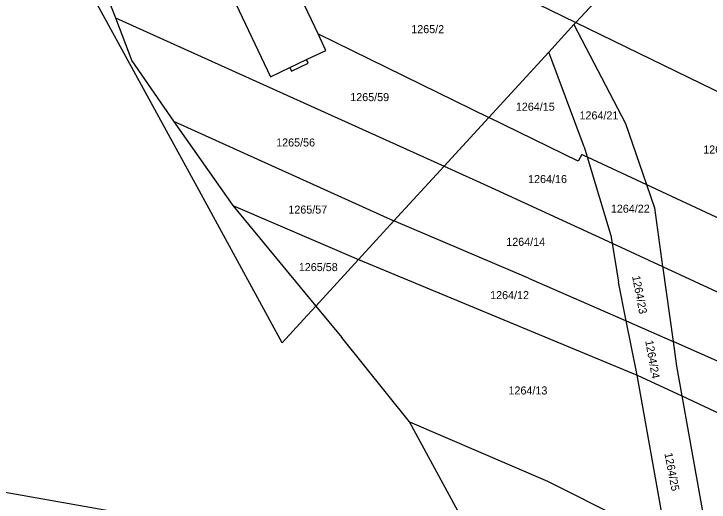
# Model space of a CAD drawing. Extents: x -779618 to -776429, y -1144546 to -1143350.
# Drawn here: x -777222.5 to -777075.6, y -1144217.4 to -1144114.1 of the extents above; entities that cross this region are included whole.
import ezdxf

# ---------------------------------------------------------------- set-up
doc = ezdxf.new("R2010")
doc.units = 0
for name, color, linetype in [('1', 7, 'Continuous'), ('11', 7, 'Continuous'), ('12', 7, 'Continuous'), ('2', 7, 'Continuous'), ('4', 7, 'Continuous')]:
    doc.layers.add(name, color=color, linetype=linetype)

msp = doc.modelspace()

# ---------------------------------------------------------------- linework, layer by layer
at = {"layer": '1'}
for p, q in [((-777158.22, -1144118.36), (-777176.03, -1144080.61)), ((-777209.36, -1144093.35), (-777201.02, -1144114.97)), ((-777103.71, -1144115.92), (-777089.82, -1144101.04)), ((-777130.33, -1144102.93), (-777103.71, -1144115.92)), ((-777183.36, -1144151.49), (-777207.58, -1144107.1)), ((-777176.85, -1144109.25), (-777168.29, -1144127.4)), ((-777201.02, -1144114.97), (-777131.57, -1144146.34)), ((-777201.02, -1144114.97), (-777197.6, -1144124.07)), ((-777109.45, -1144122.24), (-777104.14, -1144116.38)), ((-777104.14, -1144116.38), (-777103.71, -1144115.92)), ((-777104.14, -1144116.38), (-777093.24, -1144137.31)), ((-777103.71, -1144115.92), (-777052.04, -1144141.15)), ((-777158.22, -1144118.36), (-777122.09, -1144136.02)), ((-777156.57, -1144121.86), (-777158.22, -1144118.36)), ((-777160.64, -1144123.78), (-777156.57, -1144121.86)), ((-777122.09, -1144136.02), (-777109.45, -1144122.24)), ((-777101.97, -1144142.24), (-777109.45, -1144122.24)), ((-777197.6, -1144124.07), (-777188.78, -1144136.82)), ((-777160.28, -1144124.54), (-777160.64, -1144123.78)), ((-777168.29, -1144127.4), (-777164.2, -1144125.47)), ((-777164.2, -1144125.47), (-777163.84, -1144126.23)), ((-777163.84, -1144126.23), (-777160.28, -1144124.54)), ((-777188.78, -1144136.82), (-777176.23, -1144154.67)), ((-777188.78, -1144136.82), (-777142.17, -1144157.9)), ((-777131.57, -1144146.34), (-777122.09, -1144136.02)), ((-777103.26, -1144145.23), (-777122.09, -1144136.02)), ((-777093.24, -1144137.31), (-777088.81, -1144150.2)), ((-777101.97, -1144142.24), (-777101.34, -1144144.35)), ((-777102.45, -1144143.83), (-777103.26, -1144145.23)), ((-777102.45, -1144143.83), (-777101.34, -1144144.35)), ((-777101.34, -1144144.35), (-777088.81, -1144150.2)), ((-777101.34, -1144144.35), (-777096.34, -1144160.95)), ((-777142.17, -1144157.9), (-777131.57, -1144146.34)), ((-777131.57, -1144146.34), (-777121.63, -1144150.83)), ((-777088.81, -1144150.2), (-777061.29, -1144163.05)), ((-777088.81, -1144150.2), (-777087.12, -1144155.11)), ((-777165.81, -1144183.66), (-777183.36, -1144151.49)), ((-777121.63, -1144150.83), (-777096.06, -1144162.63)), ((-777176.23, -1144154.67), (-777158.69, -1144175.9)), ((-777176.23, -1144154.67), (-777149.69, -1144166.09)), ((-777087.12, -1144155.11), (-777085.38, -1144167.56)), ((-777149.69, -1144166.09), (-777142.17, -1144157.9)), ((-777113.7, -1144169.98), (-777142.17, -1144157.9)), ((-777096.34, -1144160.95), (-777096.06, -1144162.63)), ((-777096.06, -1144162.63), (-777085.38, -1144167.56)), ((-777096.06, -1144162.63), (-777094.7, -1144170.86)), ((-777158.69, -1144175.9), (-777149.69, -1144166.09)), ((-777149.69, -1144166.09), (-777090.74, -1144190.5)), ((-777085.38, -1144167.56), (-777027.97, -1144194.05)), ((-777085.38, -1144167.56), (-777085.33, -1144167.9)), ((-777085.33, -1144167.9), (-777083.17, -1144183.37)), ((-777113.7, -1144169.98), (-777093.06, -1144179.01)), ((-777093.06, -1144179.01), (-777094.7, -1144170.86)), ((-777161.32, -1144178.76), (-777158.69, -1144175.9)), ((-777158.69, -1144175.9), (-777153.18, -1144182.56)), ((-777165.81, -1144183.66), (-777161.32, -1144178.76)), ((-777093.06, -1144179.01), (-777083.17, -1144183.37)), ((-777090.74, -1144190.5), (-777093.06, -1144179.01)), ((-777138.89, -1144200.4), (-777153.18, -1144182.56)), ((-777042.1, -1144201.6), (-777083.17, -1144183.37)), ((-777083.17, -1144183.37), (-777082.44, -1144188.63)), ((-777082.44, -1144188.63), (-777081.32, -1144194.92)), ((-777090.74, -1144190.5), (-777081.32, -1144194.92)), ((-777084.46, -1144225.54), (-777090.74, -1144190.5)), ((-777081.32, -1144194.92), (-777046.01, -1144211.49)), ((-777081.32, -1144194.92), (-777076.18, -1144223.71)), ((-777138.89, -1144200.4), (-777109.73, -1144212.93)), ((-777127.4, -1144221.44), (-777138.89, -1144200.4)), ((-777109.73, -1144212.93), (-777084.46, -1144225.54))]:
    msp.add_line(p, q, dxfattribs=at)
at = {"layer": '11'}
msp.add_lwpolyline([(-777383.83, -1144125.45), (-777380.59, -1144131.49), (-777376.42, -1144139.26), (-777375.87, -1144142.98), (-777375.21, -1144147.4), (-777363.88, -1144169.2), (-777350.14, -1144189.48), (-777344.02, -1144197.88), (-777330.66, -1144206.26), (-777300.87, -1144205.35), (-777240.69, -1144212.34), (-777193.34, -1144220.76)], dxfattribs=at)
at = {"layer": '12'}
for p, q in [((-777158.22, -1144118.36), (-777176.03, -1144080.61)), ((-777176.85, -1144109.25), (-777168.29, -1144127.4)), ((-777156.57, -1144121.86), (-777158.22, -1144118.36)), ((-777160.64, -1144123.78), (-777156.57, -1144121.86)), ((-777164.2, -1144125.47), (-777160.64, -1144123.78)), ((-777168.29, -1144127.4), (-777164.2, -1144125.47))]:
    msp.add_line(p, q, dxfattribs=at)
at = {"layer": '4'}
msp.add_line((-777164.2, -1144125.47), (-777160.64, -1144123.78), dxfattribs=at)

# ---------------------------------------------------------------- texts
at = {"layer": '2'}
for s, p in [('1265/2', (-777138.51, -1144118.2)), ('1265/59', (-777151.41, -1144132.57)), ('1264/15', (-777116.4, -1144134.6)), ('1264/21', (-777102.95, -1144136.44)), ('1265/56', (-777167.07, -1144142.16)), ('1264/30', (-777076.8, -1144143.65)), ('1264/16', (-777113.82, -1144149.9)), ('1265/57', (-777164.49, -1144156.35)), ('1264/22', (-777096.32, -1144156.16)), ('1264/14', (-777118.43, -1144163.17)), ('1265/58', (-777162.28, -1144168.51)), ('1264/12', (-777121.84, -1144174.44)), ('1264/13', (-777117.96, -1144194.6))]:
    msp.add_text(s, height=1.7, dxfattribs=at).set_placement(p)
for s, rotation, p in [('1264/23', 280.8639, (-777091.84, -1144169.62)), ('1264/24', 280.1764, (-777089.07, -1144183.27)), ('1264/25', 280.9212, (-777085.01, -1144207.07))]:
    msp.add_text(s, height=1.7, rotation=rotation, dxfattribs=at).set_placement(p)

doc.saveas('drawing.dxf')
